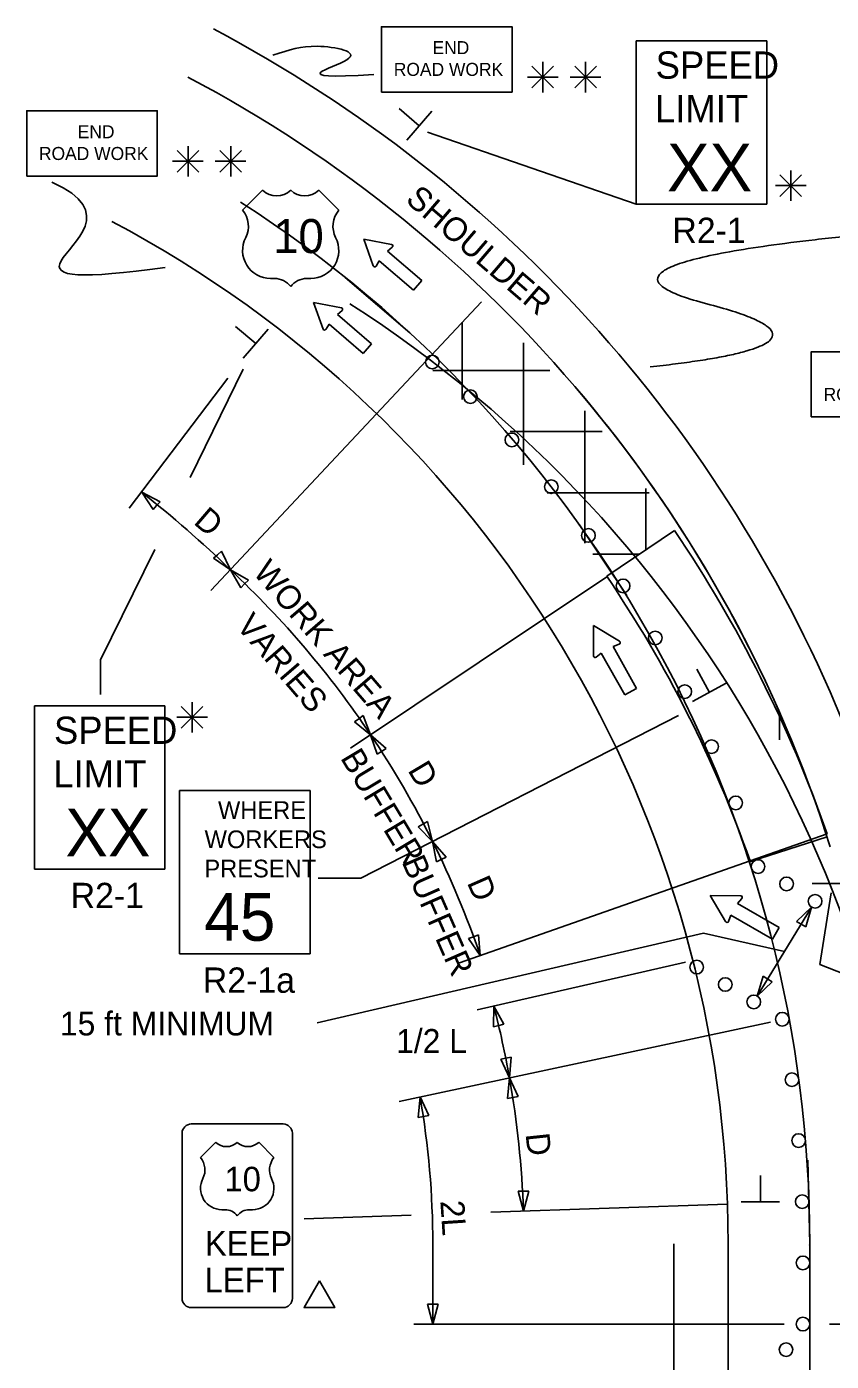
# Model space of a CAD drawing. Extents: x 16731 to 18464, y 5737 to 6974.
# Drawn here: x 16731.3 to 16967.8, y 6535 to 6927.4 of the extents above; entities that cross this region are included whole.
import ezdxf

# ---------------------------------------------------------------- set-up
doc = ezdxf.new("R2010")
doc.units = 0
for name, color, linetype in [('ALI_LEGAL_EX', 7, 'Continuous'), ('Level 3', 7, 'Continuous'), ('MT_SCRATCH_LEVEL_A', 7, 'Continuous'), ('MT_SCRATCH_LEVEL_E', 7, 'Continuous'), ('PAVT_EDGE_EX', 7, 'Continuous'), ('TRAFFIC_SIGNS_PR', 7, 'Continuous'), ('TYPICAL_EX', 7, 'Continuous'), ('TYPICAL_TEXT_DIMEN_PR', 7, 'Continuous')]:
    doc.layers.add(name, color=color, linetype=linetype)

msp = doc.modelspace()

# ---------------------------------------------------------------- linework, layer by layer
at = {"layer": 'ALI_LEGAL_EX'}
msp.add_line((16961.51, 6069.17), (16961.51, 6569.52), dxfattribs=at)
for points in [[(16843.92, 6837.36), (16824.97, 6853.66)], [(16907.75, 6760.19), (16893.85, 6780.96)], [(16961.46, 6569.17), (16961.51, 6569.52), (16960.94, 6594.16)]]:
    msp.add_lwpolyline(points, dxfattribs=at)
for centre in [(16597.51, 6569.52), (16629.65, 6539.64)]:
    msp.add_arc(centre, 364, 0, 57.2958, dxfattribs=at)
at = {"layer": 'Level 3'}
msp.add_line((16790.43, 6824.05), (16761.49, 6785.86), dxfattribs=at)
msp.add_arc((16565.31, 6535.47), 324, 45.7926, 51.9216, dxfattribs=at)
at = {"layer": 'MT_SCRATCH_LEVEL_A'}
for p, q in [((16859.36, 6817.81), (16859.36, 6840.5)), ((16877.36, 6798.6), (16877.36, 6834.49)), ((16850.68, 6826.37), (16885.07, 6826.37)), ((16895.36, 6775.6), (16895.36, 6814.5)), ((16873.48, 6808.37), (16900.47, 6808.37)), ((16884.27, 6790.37), (16914.28, 6790.37)), ((16913.36, 6773.63), (16913.36, 6791.62)), ((16897.74, 6772.37), (16911.51, 6772.37)), ((16952.6, 6717.72), (16952.6, 6725.53)), ((16943.74, 6681.84), (16966.58, 6689.25))]:
    msp.add_line(p, q, dxfattribs=at)
msp.add_arc((16597.51, 6569.52), 388, 22.6538, 40.5126, dxfattribs=at)
at = {"layer": 'MT_SCRATCH_LEVEL_E'}
for p, q in [((16838.58, 6863.36), (16830.39, 6864.94)), ((16830.39, 6864.94), (16833.2, 6857.1)), ((16837.39, 6861.41), (16838.79, 6862.55)), ((16847.44, 6852.77), (16837.39, 6861.41)), ((16834.03, 6857.02), (16834.95, 6858.57)), ((16834.95, 6858.57), (16845, 6849.93)), ((16845, 6849.93), (16847.44, 6852.77)), ((16823.83, 6844.77), (16815.64, 6846.35)), ((16815.64, 6846.35), (16818.45, 6838.51)), ((16822.64, 6842.82), (16824.04, 6843.96)), ((16819.28, 6838.43), (16820.2, 6839.98)), ((16820.2, 6839.98), (16830.25, 6831.34)), ((16832.69, 6834.17), (16822.64, 6842.82)), ((16830.25, 6831.34), (16832.69, 6834.17))]:
    msp.add_line(p, q, dxfattribs=at)
for centre, start, end in [((16838.49, 6862.91), 309.3361, 79.073), ((16833.64, 6857.26), 199.7248, 329.2637), ((16823.74, 6844.31), 309.3361, 79.073), ((16818.88, 6838.67), 199.7248, 329.2637)]:
    msp.add_arc(centre, 0.463, start, end, dxfattribs=at)
at = {"layer": 'PAVT_EDGE_EX'}
for p, q in [((16921.71, 6779.28), (16901.82, 6765.82)), ((16943.95, 6682.14), (16966.6, 6690.08)), ((16921.51, 6569.52), (16921.51, 6043.9)), ((16937.51, 6569.52), (16937.51, 6043.9))]:
    msp.add_line(p, q, dxfattribs=at)
for centre, radius, start, end in [((16597.51, 6569.52), 404, 21.0961, 62.1564), ((16597.51, 6569.52), 388, 17.5132, 62.1564), ((16597.51, 6569.52), 340, 0, 62.1564), ((16600.45, 6561.71), 388, 19.3199, 34.1071), ((16600.45, 6561.71), 363.99, 19.32, 34.1071)]:
    msp.add_arc(centre, radius, start, end, dxfattribs=at)
at = {"layer": 'TRAFFIC_SIGNS_PR'}
for p, q in [((16910.43, 6923.26), (16948.83, 6923.26)), ((16910.43, 6875.26), (16910.43, 6923.26)), ((16948.83, 6875.26), (16948.83, 6923.26)), ((16910.43, 6875.26), (16948.83, 6875.26)), ((16733.58, 6727.69), (16771.97, 6727.69)), ((16733.58, 6679.69), (16733.58, 6727.69)), ((16771.97, 6679.69), (16771.97, 6727.69)), ((16776.24, 6702.81), (16814.64, 6702.81)), ((16776.24, 6654.81), (16776.24, 6702.81)), ((16814.64, 6654.81), (16814.64, 6702.81)), ((16733.58, 6679.69), (16771.97, 6679.69)), ((16776.24, 6654.81), (16814.64, 6654.81)), ((16806.71, 6604.81), (16779.71, 6604.81)), ((16777.01, 6602.11), (16777.01, 6553.51)), ((16809.41, 6553.51), (16809.41, 6602.11)), ((16779.71, 6550.81), (16806.71, 6550.81))]:
    msp.add_line(p, q, dxfattribs=at)
for points in [[(16835.61, 6908.21), (16874.01, 6908.21), (16874.01, 6927.41), (16835.61, 6927.41)], [(16731.32, 6883.48), (16769.72, 6883.48), (16769.72, 6902.68), (16731.32, 6902.68)], [(16961.95, 6812.66), (17000.35, 6812.66), (17000.35, 6831.86), (16961.95, 6831.86)]]:
    msp.add_lwpolyline(points, close=True, dxfattribs=at)
for centre in [(16850.55, 6828.81), (16861.74, 6818.64), (16873.94, 6805.93), (16885.53, 6792.16), (16896.44, 6777.84), (16906.62, 6763.01), (16916.07, 6747.69), (16924.75, 6731.92), (16932.64, 6715.74), (16939.73, 6699.2), (16946.29, 6680.49), (16954.68, 6675.38), (16963.06, 6670.27), (16928.27, 6650.92), (16936.65, 6645.81), (16945.03, 6640.7), (16953.42, 6635.59), (16953.42, 6635.59), (16956.26, 6617.81), (16958.22, 6599.92), (16959.28, 6581.96), (16959.5, 6563.96), (16959.5, 6545.96), (16959.5, 6545.96), (16954.53, 6538.45)]:
    msp.add_circle(centre, 2, dxfattribs=at)
for centre, start, end in [((16779.71, 6602.1), 90, 180), ((16806.71, 6602.1), 0, 90), ((16779.71, 6553.5), 180, 270), ((16806.71, 6553.5), 270, 0)]:
    msp.add_arc(centre, 2.7, start, end, dxfattribs=at)
at = {"layer": 'TYPICAL_EX'}
for p, q in [((16794.78, 6873.43), (16800.67, 6879.32)), ((16823.07, 6873.43), (16817.18, 6879.32)), ((16803.02, 6853.37), (16804.2, 6853.37)), ((16814.83, 6853.37), (16813.65, 6853.37)), ((16782.41, 6594.91), (16786.91, 6599.41)), ((16804.01, 6594.91), (16799.51, 6599.41)), ((16788.7, 6579.59), (16789.6, 6579.59)), ((16797.71, 6579.59), (16796.81, 6579.59))]:
    msp.add_line(p, q, dxfattribs=at)
for centre, radius, start, end in [((16804.8, 6883.62), 5.96, 226.1404, 313.8596), ((16813.05, 6883.62), 5.96, 226.1404, 313.8596), ((16789.19, 6868.71), 7.31, 333.0977, 40.1936), ((16828.66, 6868.71), 7.31, 139.8064, 206.9023), ((16803.03, 6861.61), 8.24, 152.6698, 269.9013), ((16814.81, 6861.61), 8.24, 270.0987, 27.3302), ((16804.21, 6847.46), 5.91, 37.1038, 90.1385), ((16813.63, 6847.46), 5.91, 89.8615, 142.8962), ((16790.06, 6602.68), 4.55, 226.1404, 313.8596), ((16796.36, 6602.68), 4.55, 226.1404, 313.8596), ((16778.14, 6591.3), 5.58, 333.0977, 40.1936), ((16808.27, 6591.3), 5.58, 139.8064, 206.9023), ((16788.71, 6585.89), 6.29, 152.6698, 269.9013), ((16797.7, 6585.89), 6.29, 270.0987, 27.3302), ((16789.61, 6575.09), 4.51, 37.1038, 90.1385), ((16796.8, 6575.09), 4.51, 89.8615, 142.8962)]:
    msp.add_arc(centre, radius, start, end, dxfattribs=at)
at = {"layer": 'TYPICAL_TEXT_DIMEN_PR'}
for p, q in [((16879.85, 6915.77), (16886.22, 6909.4)), ((16886.22, 6915.77), (16879.85, 6909.4)), ((16883.03, 6912.59), (16883.03, 6917.04)), ((16892.4, 6915.77), (16898.78, 6909.4)), ((16898.78, 6915.77), (16892.4, 6909.4)), ((16895.59, 6912.59), (16895.59, 6917.04)), ((16883.03, 6912.59), (16878.5, 6912.59)), ((16883.03, 6912.59), (16886.22, 6912.59)), ((16883.03, 6912.59), (16887.51, 6912.59)), ((16883.03, 6912.59), (16883.03, 6908.09)), ((16895.59, 6912.59), (16891.06, 6912.59)), ((16895.59, 6912.59), (16898.78, 6912.59)), ((16895.59, 6912.59), (16900.07, 6912.59)), ((16895.59, 6912.59), (16895.59, 6908.09)), ((16846.69, 6898.3), (16840.79, 6903.38)), ((16850.36, 6902.57), (16843.02, 6894.04)), ((16849.17, 6896.4), (16910.43, 6875.26)), ((16775.56, 6891.04), (16781.93, 6884.67)), ((16781.93, 6891.04), (16775.56, 6884.67)), ((16778.75, 6887.85), (16778.75, 6892.31)), ((16794.49, 6891.04), (16788.11, 6884.67)), ((16788.12, 6891.04), (16794.49, 6884.67)), ((16791.3, 6887.85), (16791.3, 6892.31)), ((16778.75, 6887.85), (16774.21, 6887.85)), ((16778.75, 6887.85), (16781.93, 6887.85)), ((16778.75, 6887.85), (16783.22, 6887.85)), ((16778.75, 6887.85), (16778.75, 6883.35)), ((16791.3, 6887.85), (16786.77, 6887.85)), ((16791.3, 6887.85), (16794.49, 6887.85)), ((16791.3, 6887.85), (16795.78, 6887.85)), ((16791.3, 6887.85), (16791.3, 6883.35)), ((16952.74, 6883.87), (16959.11, 6877.5)), ((16959.11, 6883.87), (16952.74, 6877.5)), ((16955.93, 6880.69), (16955.93, 6885.14)), ((16955.93, 6880.69), (16951.39, 6880.69)), ((16955.93, 6880.69), (16959.11, 6880.69)), ((16955.93, 6880.69), (16960.4, 6880.69)), ((16955.93, 6880.69), (16955.93, 6876.19)), ((16865.03, 6846.56), (16785.49, 6761.6)), ((16798.63, 6834.22), (16792.73, 6839.3)), ((16802.3, 6838.49), (16794.96, 6829.96)), ((16779.35, 6794.9), (16794.95, 6826.72)), ((16768.45, 6785.43), (16765.13, 6790.51)), ((16765.13, 6790.51), (16770.55, 6787.76)), ((16769.5, 6786.59), (16768.45, 6785.43)), ((16770.55, 6787.76), (16769.5, 6786.59)), ((16753.06, 6741.26), (16768.99, 6773.75)), ((16787.41, 6772.17), (16788.61, 6773.19)), ((16788.61, 6773.19), (16791.22, 6767.72)), ((16786.22, 6771.15), (16787.41, 6772.17)), ((16791.22, 6767.72), (16786.22, 6771.15)), ((16794.28, 6762.47), (16791.22, 6767.72)), ((16791.22, 6767.72), (16796.49, 6764.7)), ((16902.12, 6765.9), (16826.48, 6715.26)), ((16795.38, 6763.59), (16794.28, 6762.47)), ((16796.49, 6764.7), (16795.38, 6763.59)), ((16897.96, 6751.32), (16897.9, 6742.44)), ((16905.59, 6746.74), (16897.96, 6751.32)), ((16903.68, 6745.22), (16905.5, 6745.85)), ((16910.59, 6732.88), (16903.68, 6745.22)), ((16898.71, 6742.05), (16900.2, 6743.27)), ((16900.2, 6743.27), (16907.11, 6730.93)), ((16753.06, 6731.04), (16753.06, 6741.26)), ((16932, 6731.69), (16928.3, 6738.53)), ((16936.95, 6734.36), (16927.06, 6729.01)), ((16907.11, 6730.93), (16910.59, 6732.88)), ((16776.76, 6727.57), (16783.14, 6721.2)), ((16783.14, 6727.57), (16776.76, 6721.2)), ((16779.95, 6724.39), (16779.95, 6728.84)), ((16779.95, 6724.39), (16775.42, 6724.39)), ((16779.95, 6724.39), (16783.14, 6724.39)), ((16779.95, 6724.39), (16784.43, 6724.39)), ((16779.95, 6724.39), (16779.95, 6719.89)), ((16827.68, 6723.03), (16828.94, 6723.96)), ((16832.42, 6719.24), (16827.68, 6723.03)), ((16828.94, 6723.96), (16830.2, 6724.89)), ((16922.92, 6724.85), (16829.57, 6677.05)), ((16830.2, 6724.89), (16832.42, 6719.24)), ((16834.32, 6713.48), (16832.42, 6719.24)), ((16832.42, 6719.24), (16836.95, 6715.2)), ((16835.64, 6714.34), (16834.32, 6713.48)), ((16836.95, 6715.2), (16835.64, 6714.34)), ((16846.42, 6692.2), (16847.79, 6692.96)), ((16850.64, 6687.84), (16846.42, 6692.2)), ((16847.79, 6692.96), (16849.17, 6693.72)), ((16849.17, 6693.72), (16850.64, 6687.84)), ((16851.79, 6681.88), (16850.64, 6687.84)), ((16850.64, 6687.84), (16854.61, 6683.25)), ((16853.2, 6682.56), (16851.79, 6681.88)), ((16854.61, 6683.25), (16853.2, 6682.56)), ((16858.54, 6652.2), (16943.94, 6682.14)), ((16829.57, 6677.05), (16817.01, 6677.07)), ((16973.49, 6675.48), (16962.24, 6675.48)), ((16941.15, 6671.92), (16932.25, 6671.94)), ((16932.25, 6671.94), (16936.76, 6664.29)), ((16940.29, 6669.64), (16941.52, 6671.12)), ((16967.78, 6672.77), (16964.45, 6651.69)), ((16952.55, 6662.6), (16940.29, 6669.64)), ((16946.08, 6642.4), (16962.02, 6668.56)), ((16957.63, 6664.37), (16962.02, 6668.56)), ((16962.02, 6668.56), (16960.31, 6662.74)), ((16963.06, 6670.27), (16963.06, 6670.27)), ((16937.65, 6664.37), (16938.3, 6666.18)), ((16938.3, 6666.18), (16950.56, 6659.13)), ((16958.97, 6663.56), (16957.63, 6664.37)), ((16960.31, 6662.74), (16958.97, 6663.56)), ((16930.24, 6660.9), (16816.71, 6634.55)), ((16861.17, 6659.31), (16862.64, 6659.85)), ((16864.65, 6654.34), (16861.17, 6659.31)), ((16862.64, 6659.85), (16864.12, 6660.38)), ((16864.12, 6660.38), (16864.65, 6654.34)), ((16954.05, 6655.48), (16930.24, 6660.9)), ((16950.56, 6659.13), (16952.55, 6662.6)), ((16924.96, 6652.39), (16863.76, 6638.33)), ((16964.45, 6651.69), (17046.11, 6619.48)), ((16946.08, 6642.4), (16947.78, 6648.23)), ((16947.78, 6648.23), (16949.13, 6647.41)), ((16949.13, 6647.41), (16950.47, 6646.59)), ((16950.47, 6646.59), (16946.08, 6642.4)), ((16868.58, 6633.38), (16868.64, 6639.45)), ((16868.64, 6639.45), (16871.62, 6634.16)), ((16840.84, 6611.45), (16949.94, 6634.73)), ((16870.1, 6633.77), (16868.58, 6633.38)), ((16871.62, 6634.16), (16870.1, 6633.77)), ((16870.65, 6623.86), (16872.19, 6624.13)), ((16873.22, 6618.36), (16870.65, 6623.86)), ((16872.19, 6624.13), (16873.74, 6624.4)), ((16873.74, 6624.4), (16873.22, 6618.36)), ((16872.69, 6612.31), (16873.22, 6618.36)), ((16873.22, 6618.36), (16875.79, 6612.86)), ((16846.44, 6606.71), (16846.97, 6612.76)), ((16846.97, 6612.76), (16849.54, 6607.26)), ((16874.24, 6612.59), (16872.69, 6612.31)), ((16875.79, 6612.86), (16874.24, 6612.59)), ((16847.99, 6606.98), (16846.44, 6606.71)), ((16849.54, 6607.26), (16847.99, 6606.98)), ((16946.99, 6581.91), (16946.99, 6589.7)), ((16877.34, 6579.16), (16875.77, 6585.02)), ((16875.77, 6585.02), (16877.34, 6585.02)), ((16877.34, 6585.02), (16878.91, 6585.02)), ((16878.91, 6585.02), (16877.34, 6579.16)), ((16867.78, 6578.83), (16937.31, 6581.22)), ((16952.61, 6581.91), (16941.36, 6581.91)), ((16812.87, 6576.94), (16844.31, 6578.02)), ((16850.69, 6569.52), (16850.69, 6545.96)), ((16850.69, 6545.96), (16849.12, 6551.82)), ((16849.12, 6551.82), (16850.69, 6551.82)), ((16850.69, 6551.82), (16852.26, 6551.82)), ((16852.26, 6551.82), (16850.69, 6545.96)), ((16954.01, 6545.96), (16845.14, 6545.96)), ((16967.28, 6545.96), (17074.51, 6545.96))]:
    msp.add_line(p, q, dxfattribs=at)
msp.add_lwpolyline([(16817.37, 6558.64), (16812.84, 6550.81), (16821.89, 6550.81)], close=True, dxfattribs=at)
for centre, radius, start, end in [((16599.85, 6563.32), 280, 33.8403, 46.8862), ((16905.32, 6746.32), 0.494, 289.2925, 59.0295), ((16898.4, 6742.44), 0.494, 179.6812, 309.2202), ((16599.85, 6563.32), 280, 26.4049, 33.8392), ((16599.85, 6563.32), 280, 26.4049, 26.7689), ((16599.85, 6563.32), 280, 18.9703, 26.4049), ((16941.14, 6671.42), 0.494, 320.1573, 89.8942), ((16937.18, 6664.54), 0.494, 210.5459, 340.0849), ((16597.51, 6569.52), 280, 10.0461, 14.4629), ((16597.51, 6569.52), 280, 1.9734, 10.046), ((16597.51, 6569.52), 253.18, 0, 9.834)]:
    msp.add_arc(centre, radius, start, end, dxfattribs=at)
for points, degree in [([(16803.72, 6919.07), (16808.92, 6920.57), (16814.41, 6922.95), (16836.9, 6918.75), (16806.08, 6911.66), (16833.38, 6913.34)], 3), ([(16771.98, 6856.64), (16747.25, 6853.23), (16730.03, 6854), (16758.34, 6873.13), (16738.73, 6881.66)], 3), ([(16914.62, 6827.39), (16976.79, 6834.13), (16886.34, 6857.55), (16979.34, 6866.49)], 2)]:
    msp.add_open_spline(points, degree=degree, dxfattribs=at)

# ---------------------------------------------------------------- texts
at = {"layer": 'TRAFFIC_SIGNS_PR'}
for s, height, p in [('END', 3.831, (16850.61, 6919.34)), ('SPEED', 8, (16916.2, 6912.13)), ('ROAD WORK', 3.831, (16839.22, 6912.95)), ('LIMIT', 8, (16916.04, 6899.33)), ('END', 3.831, (16746.32, 6894.61)), ('ROAD WORK', 3.831, (16734.93, 6888.22)), ('XX', 14.031, (16919.54, 6879.02)), ('R2-1', 7.44, (16921.11, 6863.82)), ('ROAD WORK', 3.831, (16965.56, 6817.4)), ('SPEED', 8, (16739.34, 6716.56)), ('LIMIT', 8, (16739.18, 6703.76)), ('WHERE', 5.2, (16787.55, 6694.5)), ('XX', 14.031, (16742.69, 6683.45)), ('WORKERS', 5.2, (16783.62, 6685.9)), ('PRESENT', 5.2, (16783.55, 6677.3)), ('R2-1', 7.44, (16744.25, 6668.26)), ('45', 14.031, (16783.54, 6658.67)), ('R2-1a', 7.44, (16783.09, 6643.37)), ('10', 7.2, (16789.45, 6585.01)), ('KEEP', 7.2, (16783.69, 6566.11)), ('LEFT', 7.2, (16783.59, 6555.31))]:
    msp.add_text(s, height=height, dxfattribs=at).set_placement(p)
at = {"layer": 'TYPICAL_EX'}
msp.add_text('10', height=10, dxfattribs=at).set_placement((16803.77, 6860.85))
at = {"layer": 'TYPICAL_TEXT_DIMEN_PR'}
for s, rotation, p in [('SHOULDER', 319.2839, (16842.35, 6876.07)), ('D', 319.3547, (16780.07, 6781.44)), ('WORK AREA', 310.7541, (16797.58, 6766.82)), ('VARIES', 310.7541, (16792.61, 6751.13)), ('BUFFER', 300.9582, (16823.37, 6712.43)), ('D', 300.9582, (16843.16, 6708.8)), ('BUFFER', 293.7043, (16841.46, 6681.88)), ('D', 293.7043, (16860.63, 6675.78)), ('D', 276.0098, (16877.95, 6601.84)), ('2L', 273.8016, (16852.9, 6582.16))]:
    msp.add_text(s, height=7, rotation=rotation, dxfattribs=at).set_placement(p)
for s, p in [('15 ft MINIMUM', (16741.09, 6630.83)), ('1/2 L', (16839.91, 6625.71))]:
    msp.add_text(s, height=7, dxfattribs=at).set_placement(p)

doc.saveas('drawing.dxf')
